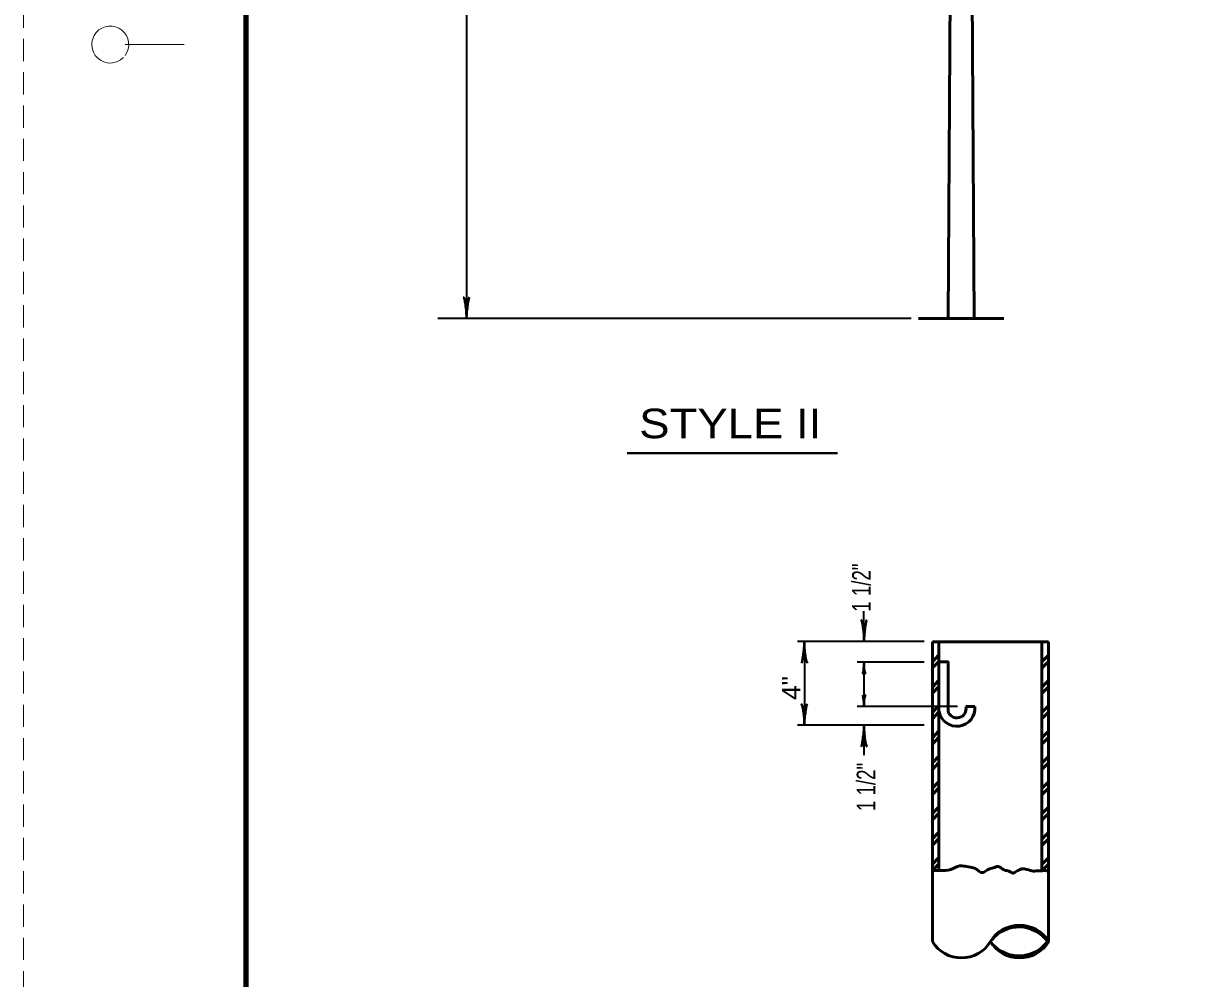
# Model space of a CAD drawing. Extents: x 6488 to 7168, y 276 to 716.
# Drawn here: x 6487.6 to 6645, y 436 to 565.2 of the extents above; entities that cross this region are included whole.
import ezdxf

# ---------------------------------------------------------------- set-up
doc = ezdxf.new("R2010")
doc.units = 0
doc.linetypes.add('MEDIUM_DASHED', pattern=[4.5, 3, -1.5])
doc.layers.add('1', color=7, linetype='Continuous', lineweight=35)
doc.layers.add('61', color=7, linetype='Continuous', lineweight=35)

msp = doc.modelspace()

# ---------------------------------------------------------------- linework, layer by layer
at = {"layer": '1', "linetype": 'MEDIUM_DASHED', "lineweight": 13}
msp.add_line((6487.643, 716.04), (6487.583, 276), dxfattribs=at)
at = {"layer": '1'}
for p, q in [((6547.486, 674.006), (6547.486, 525.256)), ((6607.592, 525.256), (6543.592, 525.256)), ((6601.205, 481.646), (6601.205, 485.666)), ((6609.325, 481.566), (6592.205, 481.566)), ((6593.145, 481.566), (6593.145, 470.266)), ((6609.325, 478.806), (6600.265, 478.806)), ((6601.205, 478.806), (6601.205, 472.806)), ((6613.825, 472.806), (6600.265, 472.806)), ((6609.325, 470.266), (6592.205, 470.266)), ((6601.205, 470.246), (6601.205, 466.226))]:
    msp.add_line(p, q, dxfattribs=at)
at = {"layer": '1', "lineweight": 53}
for p, q in [((6615.342, 653.756), (6616.092, 525.256)), ((6613.322, 650.256), (6612.592, 525.256)), ((6608.592, 525.256), (6620.092, 525.256)), ((6610.445, 481.546), (6626.165, 481.546)), ((6611.345, 481.546), (6611.345, 450.646)), ((6625.265, 481.546), (6625.265, 450.606)), ((6626.165, 481.546), (6626.165, 441.026)), ((6610.445, 478.846), (6611.345, 479.766)), ((6610.445, 478.006), (6611.345, 478.906)), ((6625.265, 478.826), (6626.165, 479.746)), ((6625.265, 477.966), (6626.165, 478.886)), ((6610.445, 475.426), (6611.345, 476.346)), ((6610.445, 474.586), (6611.345, 475.486)), ((6625.265, 475.406), (6626.165, 476.306)), ((6625.265, 474.546), (6626.165, 475.466)), ((6610.445, 472.006), (6611.345, 472.926)), ((6614.985, 472.786), (6616.185, 472.786)), ((6625.265, 471.986), (6626.165, 472.886)), ((6610.445, 471.146), (6611.345, 472.066)), ((6625.265, 471.126), (6626.165, 472.046)), ((6610.445, 468.586), (6611.345, 469.506)), ((6625.265, 468.566), (6626.165, 469.466)), ((6610.445, 467.726), (6611.345, 468.646)), ((6625.265, 467.706), (6626.165, 468.626)), ((6610.445, 465.166), (6611.345, 466.066)), ((6625.265, 465.146), (6626.165, 466.046)), ((6610.445, 464.306), (6611.345, 465.226)), ((6625.265, 464.286), (6626.165, 465.206)), ((6610.445, 461.746), (6611.345, 462.646)), ((6610.445, 460.886), (6611.345, 461.806)), ((6625.265, 461.726), (6626.165, 462.626)), ((6625.265, 460.866), (6626.165, 461.766)), ((6610.445, 458.326), (6611.345, 459.226)), ((6610.445, 457.466), (6611.345, 458.386)), ((6625.265, 458.306), (6626.165, 459.206)), ((6625.265, 457.446), (6626.165, 458.346)), ((6610.445, 454.906), (6611.345, 455.806)), ((6610.445, 454.046), (6611.345, 454.966)), ((6625.265, 454.886), (6626.165, 455.786)), ((6625.265, 454.026), (6626.165, 454.926)), ((6610.445, 451.486), (6611.345, 452.386)), ((6625.265, 451.466), (6626.165, 452.366)), ((6610.445, 450.626), (6611.345, 451.526)), ((6625.265, 450.606), (6626.165, 451.506)), ((6620.125, 442.726), (6620.185, 442.586)), ((6620.685, 442.966), (6620.765, 442.806)), ((6624.045, 442.866), (6623.945, 442.666)), ((6624.585, 442.586), (6624.485, 442.406)), ((6622.045, 439.086), (6622.205, 438.826)), ((6622.725, 439.126), (6622.865, 438.866)), ((6624.985, 440.026), (6625.085, 439.826)), ((6625.465, 440.406), (6625.565, 440.246))]:
    msp.add_line(p, q, dxfattribs=at)
at = {"layer": '1', "lineweight": 40}
msp.add_line((6569.204, 507.054), (6597.626, 507.054), dxfattribs=at)
at = {"layer": '1', "lineweight": 53}
for points in [[(6610.445, 481.546), (6610.445, 450.626), (6610.445, 441.026)], [(6611.345, 478.826), (6612.565, 478.826), (6612.565, 472.186)]]:
    msp.add_lwpolyline(points, dxfattribs=at)
for centre, radius, start, end in [((6613.765, 472.566), 2.435, 190.86929, 5.14039), ((6613.764, 472.512), 1.247, 195.45934, 12.61314), ((6622.238, 438.625), 4.61, 31.48112, 148.51888), ((6622.152, 438.228), 4.781, 35.97027, 140.35792), ((6614.376, 443.44), 4.61, 211.48112, 328.51888), ((6622.238, 443.44), 4.61, 211.48112, 328.51888), ((6622.138, 443.948), 4.854, 221.44282, 323.1281)]:
    msp.add_arc(centre, radius, start, end, dxfattribs=at)
at = {"layer": '1', "lineweight": 40}
for centre, major_axis, ratio, start_param, end_param in [((6547.21, 526.347), (0.156, -1.786), 0.122415, 0.8963533, 3.1415927), ((6547.698, 526.377), (-0.176, -1.756), 0.07063, 3.1407148, 5.41811), ((6600.935, 482.738), (0.157, -1.8), 0.122415, 0.8963533, 3.1415927), ((6601.427, 482.767), (-0.177, -1.77), 0.07063, 3.1407148, 5.41811), ((6592.931, 480.438), (0.177, 1.77), 0.07063, 3.1407148, 5.41811), ((6593.423, 480.468), (-0.157, 1.8), 0.122415, 0.8963533, 3.1415927), ((6601.004, 477.66), (0.177, 1.77), 0.07063, 4.7093373, 5.41811), ((6601.495, 477.69), (-0.157, 1.8), 0.122415, 0.8963533, 1.5837952), ((6601.186, 479.019), (0.177, 1.77), 0.07063, 3.1407148, 3.8293255), ((6601.298, 479.038), (-0.157, 1.8), 0.122415, 2.4431075, 3.1415927), ((6601.174, 472.581), (0.177, -1.77), 0.07063, 2.4538598, 3.1424706), ((6600.992, 473.939), (0.177, -1.77), 0.07063, 0.8650754, 1.573848), ((6601.484, 473.91), (-0.157, -1.8), 0.122415, 4.6993901, 5.386832), ((6601.287, 472.561), (-0.157, -1.8), 0.122415, 3.1415927, 3.8400778), ((6592.866, 471.363), (0.157, -1.8), 0.122415, 0.8963533, 3.1415927), ((6593.358, 471.392), (-0.177, -1.77), 0.07063, 3.1407148, 5.41811), ((6601, 469.121), (0.177, 1.77), 0.07063, 3.1407148, 5.41811), ((6601, 469.121), (0.177, 1.77), 0.07063, 3.1407148, 5.41811), ((6601.492, 469.15), (-0.157, 1.8), 0.122415, 0.8963533, 3.1415927), ((6601.492, 469.15), (-0.157, 1.8), 0.122415, 0.8963533, 3.1415927)]:
    msp.add_ellipse(centre, major_axis=major_axis, ratio=ratio, start_param=start_param, end_param=end_param, dxfattribs=at)
at = {"layer": '1', "lineweight": 53}
msp.add_spline([(6610.445, 450.626), (6611.445, 450.646), (6612.965, 450.786), (6614.125, 451.246), (6614.825, 451.206), (6615.805, 451.026), (6616.405, 450.826), (6616.845, 450.466), (6617.185, 450.346), (6617.505, 450.466), (6618.065, 450.806), (6618.665, 450.986), (6619.345, 451.186), (6619.885, 450.866), (6620.205, 450.686), (6620.805, 450.526), (6621.425, 450.286), (6621.625, 450.426), (6622.185, 450.706), (6622.645, 450.866), (6623.425, 450.726), (6623.725, 450.646), (6624.085, 450.546), (6624.445, 450.566), (6624.845, 450.566), (6625.305, 450.606), (6625.545, 450.646), (6625.985, 450.586), (6626.165, 450.586)], degree=3, dxfattribs=at)
at = {"layer": '61', "lineweight": 13}
msp.add_line((6501.343, 562.28), (6509.343, 562.28), dxfattribs=at)
at = {"layer": '61', "lineweight": 158}
msp.add_lwpolyline([(7156.683, 706.04), (6517.643, 706.04), (6517.643, 286.02)], dxfattribs=at)
at = {"layer": '61', "lineweight": 13}
msp.add_arc((6499.341, 562.281), 2.5, 323.13009, 315.37577, dxfattribs=at)

# ---------------------------------------------------------------- texts
at = {"layer": '1', "width": 1.15}
msp.add_text('STYLE II', height=4, dxfattribs=at).set_placement((6570.824, 509.063))
at = {"layer": '1'}
for s, width, p in [('1 1/2"', 0.75, (6602.125, 485.606)), ('4"', 1.05, (6592.625, 473.686)), ('1 1/2"', 0.75, (6602.745, 458.666))]:
    msp.add_text(s, height=2.52, rotation=90, dxfattribs=dict(at, width=width)).set_placement(p)

doc.saveas('drawing.dxf')
